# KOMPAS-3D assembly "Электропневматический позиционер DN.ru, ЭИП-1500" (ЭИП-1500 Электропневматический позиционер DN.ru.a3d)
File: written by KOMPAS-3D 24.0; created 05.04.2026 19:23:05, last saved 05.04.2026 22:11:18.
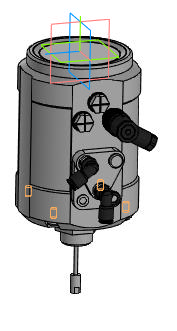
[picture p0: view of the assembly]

Document properties: Автор: R2D2; Полное имя файла: E:\Работа\Зайцев\Аксессуары для пневмоприводов\Электропневматические позиционеры DN.ru\ЭИП Электропневматический позиционер DN.ru\ЭИП-1500 Электропневматический позиционер DN.ru\5-25\ЭИП-1500 Электропневматический позиционер DN.ru.a3d

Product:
- Component [detail]: корпус  | qty 1  | pos. 1  | Масса: 7.921649; Раздел спецификации: Прочие изделия; Примечание: D900-02741; Автор: R2D2; source file: Корпус.m3d
- Component [detail]: Тело 13  | qty 1  | pos. 2  | Масса: 0.071173; source file: Г клема.m3d
- Component [detail]: Клема  | qty 1  | pos. 3  | Масса: 0.013338; source file: Клема.m3d
- Component [detail]: Тело 12  | qty 1  | pos. 4  | Масса: 0.022159; source file: Пневматический разъем.m3d
- Component [detail]: Тело 12  | qty 1  | pos. 5  | Масса: 0.022159; source file: Пневматический разъем.m3d
- Component [detail]: Тело 12  | qty 1  | pos. 6  | Масса: 0.022159; source file: Пневматический разъем.m3d
- Component [standard]: Cheese head screw ISO 7048 - М6 x 10 - H  | qty 4  | Материал: Не определено (density 0 kg/m3); Масса: 0.00392; Раздел спецификации: Стандартные изделия; Рассекать на разрезах: no
- Component [detail]: шток  | qty 1  | Масса: 0.134738; source file: шток.m3d
- Part/product: Электропневматический позиционер DN.ru  | designation ЭИП-1500
    Масса: 0.14
    Раздел спецификации: Прочие изделия
    Примечание: D900-02741

Expressions: D900-02741
Referenced files in E:\Работа\Зайцев\Аксессуары для пневмоприводов\Электропневматические позиционеры DN.ru\ЭИП Электропневматический позиционер DN.ru\ЭИП-1500 Электропневматический позиционер DN.ru\5-25\: Корпус.m3d, Г клема.m3d, Клема.m3d, Пневматический разъем.m3d, шток.m3d
Referenced files in C:\Program Files\ASCON\KOMPAS-3D v24\Libs\PolynomLib\DATA\vault\Methods\Kompas\3D\: PLib_Screw_ISO_7048_1500.m3d
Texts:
  Cheese head screw
  BOSimple***PART:5dfe4ae6-934c-9717-4054-6a9437cf2718***SHORTLOC:B94B_D4FD7824BC314902[H;1;10;6;-;Undefined]
  Программные изделия  и базы данных
  ЭИП-1500
  Тело 12 (1)
  Тело 12 (2)
  Тело 12 (3)
  Cheese head screw ISO 7048 - М6 x 10 - H (1)
  Cheese head screw ISO 7048 - М6 x 10 - H (2)
  Cheese head screw ISO 7048 - М6 x 10 - H (4)
  Cheese head screw ISO 7048 - М6 x 10 - H (6)
  Плоскость XY.Начало координат
  Ось Y.Начало координат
